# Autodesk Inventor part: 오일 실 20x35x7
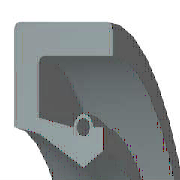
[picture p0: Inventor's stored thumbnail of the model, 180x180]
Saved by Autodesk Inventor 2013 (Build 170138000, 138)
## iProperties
IsCustomPart: 1
Created: 2012-02
Part Number: 오일 실 20x35x7
Material: 고무
Description: 회전 샤프트 립 유형 실 2 - 금속 케이스
Document SubType Name: Modeling
Standard: ISO 6194/1
Designer: mduedu
Standards Organization: ISO
Language: ko-KR
Size Designation: 20x35x7-유형 2
Categories: <MemberInstance><Categories><Category DisplayName="샤프트 부품" InternalName="7f7aeb1f-a693-4053-b835-cee3144e0d98" Mnemonic="SHFT"><Category DisplayName="실링" Intern
Density: 0.93 g/cm^3
Author: mduedu
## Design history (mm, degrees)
node "WorkPlane2"
node "WorkPoint1"
node "WorkPlane3"
body "Solid1"
node "스케치1"
revolve "회전1" stored, may be unused: angle "d37" = 360 deg
fillet "모깎기1" dims "d38" = 0.35 (= 0.05 x b)
sketch "스케치2"
  geometry: L1 (16, -0.35)-(16.8, -0.35); L2 (16, 0)-(16, -0.35); L3 (17.5, 0)-(16, 0); L4 (17.5, -7)-(17.5, 0); L5 (12.22, -7)-(17.5, -7); L6 (11.283, -4.2)-(12.22, -7); L7 (10.601, -3.72)-(11.283, -4.2); L8 (10, -1.925)-(10.601, -3.72); L9 (10.789, -1.05)-(10, -1.925); L10 (12.664, -1.05)-(10.789, -1.05); L11 (12.664, -1.925)-(12.664, -1.05); L12 (12.664, -5.6)-(12.664, -3.325); L13 (13.664, -5.6)-(12.664, -5.6); L14 (13.664, -6.3)-(13.664, -5.6); L15 (16.8, -6.3)-(13.664, -6.3); L16 (16.8, -0.35)-(16.8, -6.3); L17 (0, -15.959)-(0, 2.029); L18 (0, -15.959)-(0, 2.029); L19 (0, -19.557)-(0, 5.626) reference; L20 (-5.2, 0)-(31.2, 0) reference; A1 r 0.7 centre (12.664, -2.625) between (12.664, -3.325) and (12.664, -1.925)
  constraints: 36 end point, 7 vertical, 6 horizontal, 2 collinear, 2 point on circle, 1 centre point, 1 parallel, 1 point on line
  dimensions: "d2" = 0.35 distance of L2.start L1.start (= 0.05 x b); "d4" = 7 distance of L4.start L3.start (= b); "d6" = 0.7 horizontal distance of L1.end L3.start (= 0.1 x b); "d8" = 0.7 horizontal distance of L15.start L4.start (= 0.1 x b); "d10" = 0.7 distance of L14.start L13.start (= 0.1 x b); "d12" = 0.7 vertical distance of L1.end L10.start (= 0.1 x b); "d14" = 0.875 distance of L11.start L10.start (= 0.125 x b); "d16" = 0.7 radius of A1 (= 0.1 x b); "d18" = 0 horizontal distance of A1.centre L12.end; "d20" = 0.875 vertical distance of L9.start L8.start (= 0.125 x b); "d22" = 1.79487 vertical distance of L8.start L7.start (= 0.25641 x b); "d24" = 2.8 vertical distance of L6.start L5.start (= 0.4 x b); "d26" = 1.5 distance of L3.start L2.start (= 0.1 x dd - 0.1 x Diam); "d28" = 0.78947 horizontal distance of L9.start L8.start (= 0.0526316 x dd - 0.0526316 x Diam); "d30" = 1.875 distance of L10.start L9.start (= 0.125 x dd - 0.125 x Diam); "d32" = 1 distance of L13.start L12.start (= 0.0666667 x dd - 0.0666667 x Diam); "d34" = 0.9375 horizontal distance of L6.start L5.start (= 0.0625 x dd - 0.0625 x Diam); "d36" = 0.68182 horizontal distance of L7.start L6.start (= 0.0454545 x dd - 0.0454545 x Diam); "msp_d39" = 20 diameter of L8.start L17 (= Diam); "msp_d40" = 35 diameter of L4 L17 (= dd)
other parameters: "dd" = 35 [user parameter; used in 7 equation terms], "Diam" = 20 [user parameter; used in 7 equation terms], "b" = 7 [user parameter; used in 13 equation terms], "d0" = -7 (computed from b), "d1" = 0.4 (derived), "d3" = 8 (derived), "d5" = 0.8 (derived), "d7" = 0.8 (derived), "d9" = 0.8 (derived), "d11" = 0.8 (derived), "d13" = 1 (derived), "d15" = 0.8 (derived), "d17" = 0 (derived), "d19" = 1 (derived), "d21" = 2.05128 (derived), "d23" = 3.2 (derived), "d25" = 2 (derived), "d27" = 1.05263 (derived), "d29" = 2.5 (derived), "d31" = 1.33333 (derived), "d33" = 1.25 (derived), "d35" = 0.90909 (derived), "d42" = 0
